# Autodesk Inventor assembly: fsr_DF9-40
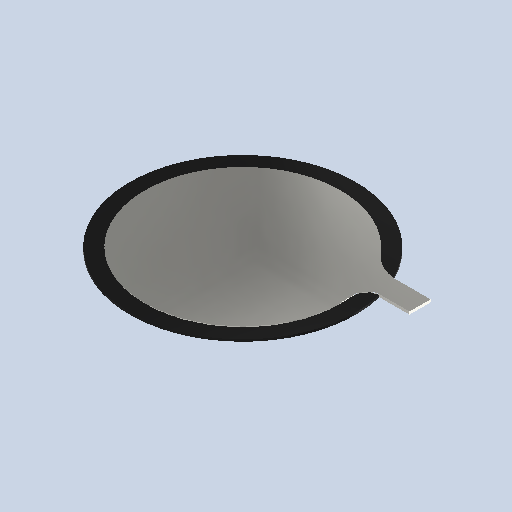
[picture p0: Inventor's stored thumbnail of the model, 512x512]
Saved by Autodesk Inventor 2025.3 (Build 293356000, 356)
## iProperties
Created: 2018-09
Part Number: fsr_DF9-40
Document SubType Name: Assembly
Designer: Ev
Mass: 0.0700802 g
Surface Area: 2.91753 cm^2
Volume: 0.0153265 cm^3
Density: 4.57248 g/cm^3
Author: Ev
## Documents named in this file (3)
- C:\Users\Luis M\Desktop\TESIS\CAD_TESIS\fsr_DF9-40.iam
- C:\Users\Luis M\Desktop\TESIS\CAD_TESIS\cad\DF9-40 Force Sensitive Resistor\conductor.ipt
- C:\Users\Luis M\Desktop\TESIS\CAD_TESIS\cad\DF9-40 Force Sensitive Resistor\electrode1.ipt
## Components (2 placed, 2 different names)
1. conductor:1
2. electrode1:1
